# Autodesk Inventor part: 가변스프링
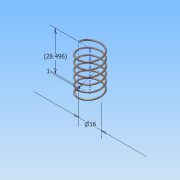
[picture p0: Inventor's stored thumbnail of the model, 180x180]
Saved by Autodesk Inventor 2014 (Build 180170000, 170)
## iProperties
Created: 2016-05
Part Number: 가변스프링
Material: 스테인레스 스틸
Document SubType Name: Modeling
Designer: 703-04
Mass: 1.90231 g
Surface Area: 9.49569 cm^2
Volume: 0.235434 cm^3
Density: 8.08 g/cm^3
Appearance: 반연마
Author: 703-04
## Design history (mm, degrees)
sketch "스케치2"
  geometry: L1 (0, 0)-(8, 0); L2 (8, 0)-(8, 28.496); L3 (8, 28.496)-(0, 28.496); L4 (0, 28.496)-(0, 0); C1 r 0.5 at (8, 0)
  constraints: 8 end point, 2 parallel, 1 centre point, 1 coincident, 1 horizontal, 1 perpendicular
  dimensions: "d0" = 1 diameter of C1; "d1" = 28.49646 distance of L1.end L2.end (derived); "d2" = 16 diameter of L2 L4
feature "코일1" pitch "d3" = 10; turns "d5" = 6; dims "d4" = 28.49646 (= d1), "d6" = 0, angle "d7" = 90 deg, angle "d8" = 90 deg, "d9" = 0, "d10" = 0
sketch "스케치3"
  geometry: L1 (-8.5, 0)-(-7.5, 0) reference; 1 further point
  constraints: 1 horizontal alignment
extrude "돌출1" cut sketch "스케치3" stored distance "d11" = 10; taper "d12" = 0 deg
node "작업 평면1"
sketch "스케치4"
  geometry: L1 (-7.5, 0)-(-8.5, 0) reference; 1 further point
  constraints: 1 horizontal alignment
extrude "돌출2" cut sketch "스케치4" stored distance "d13" = 10; taper "d14" = 0 deg
node "솔리드1"
node "절단 모서리 투영1"
node "절단 모서리 투영2"
